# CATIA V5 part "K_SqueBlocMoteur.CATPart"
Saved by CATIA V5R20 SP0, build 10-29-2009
Part number: Squelette_bloc_moteur
Publications: "Axe_pivot_bloc_moteur", "Plan_bloc_moteur"
Bounding box of the stored display mesh (mm): x -171 to -131, y -142.303 to -142.303, z 0 to 0
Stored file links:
  G:\Khaled_CFAO_2011\ST2M\ST2M_GR2\jcoetard\Khaled\CAD_CATIA\K_SqueBlocMoteur.CATPart
  G:\Khaled_CFAO_2011\ST2M\ST2M_GR2\jcoetard\jcoetard\Maquette_jcoetard\Squelette_socle_bati.CATPart
  G:\Khaled_CFAO_2011\ST2M\ST2M_GR2\jcoetard\Khaled\CAD_CATIA\K_Squelette.CATProduct
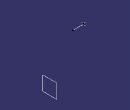
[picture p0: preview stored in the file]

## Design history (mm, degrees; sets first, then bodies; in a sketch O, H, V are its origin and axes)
Set1
  Point1 "Point_centre_écrou": linked copy from another document
Set2 "Set géométrique"
  Plane1 "Plan_bloc_moteur": type Offset, RefPlane yz-plane, Offset 100
  Line1 "Axe_pivot_bloc_moteur": type Normal, RefPoint Point1, RefSkin Plane1, Start 0, End 40
Body1 (main body)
